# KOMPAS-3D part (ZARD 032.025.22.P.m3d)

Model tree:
1. Плоскость XY
2. Плоскость ZX
3. Плоскость ZY
4. Ось X
5. Ось Y
6. Ось Z
7. Начало координат
8. Булева операция:5
9. Булева операция:6
10. Булева операция:7
11. Булева операция:8
